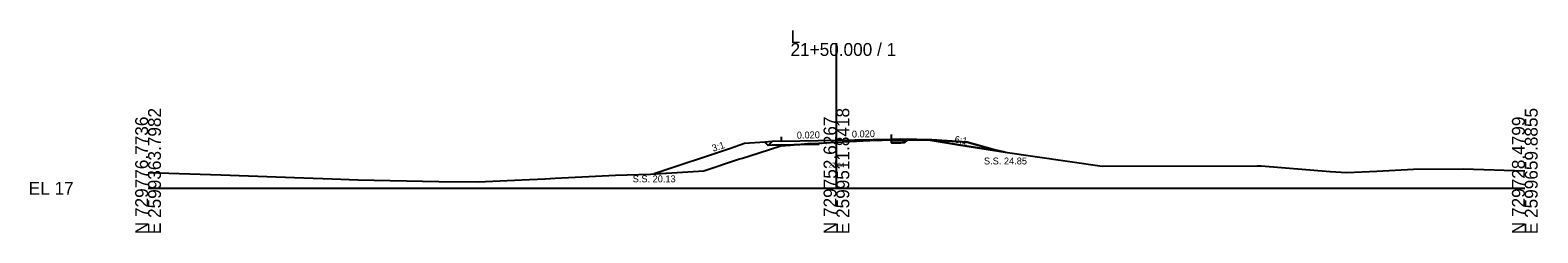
# Model space of a CAD drawing. Extents: x -26 to 3303, y -10 to 9555.
# Drawn here: x 1974.3 to 2302.8, y 2990.3 to 3034.4 of the extents above; entities that cross this region are included whole.
import ezdxf

# ---------------------------------------------------------------- set-up
doc = ezdxf.new("R2010")
doc.units = 0
for name, color, linetype in [('Exist Cross Section Cell', 7, 'Continuous'), ('Exist XS Center Line Elevation Label', 7, 'Continuous'), ('Exist XS Ground Line', 7, 'Continuous'), ('Prop XS Ditch Slope Text', 7, 'Continuous'), ('Prop XS Dump Level', 7, 'Continuous'), ('Prop XS Earthwork Shape', 7, 'Continuous'), ('Prop XS EOT Tick Mark', 7, 'Continuous'), ('Prop XS Finish Grade', 7, 'Continuous'), ('Prop XS Finish Grade Earthwork', 7, 'Continuous'), ('Prop XS Finish Grade Paved Shoulder', 7, 'Continuous'), ('Prop XS Finish Grade Pavement', 7, 'Continuous'), ('Prop XS Pvmt Edge Slope', 7, 'Continuous'), ('Prop XS SE Text', 7, 'Continuous'), ('Prop XS Side Slope Text', 7, 'Continuous'), ('Prop XS SS Elevation Text', 7, 'Continuous'), ('Prop XS Subgrade Earthwork', 7, 'Continuous')]:
    doc.layers.add(name, color=color, linetype=linetype)

msp = doc.modelspace()

# ---------------------------------------------------------------- linework, layer by layer
at = {"layer": 'Exist Cross Section Cell'}
for p, q in [((2150, 3000), (2150, 3031.61)), ((2000, 3000), (2150, 3000)), ((2150, 3000), (2300, 3000))]:
    msp.add_line(p, q, dxfattribs=at)
at = {"layer": 'Exist XS Ground Line'}
msp.add_lwpolyline([(2000, 3003.47), (2015.86, 3002.95), (2033.96, 3002.26), (2040.14, 3002.02), (2045.7, 3001.81), (2063.36, 3001.5), (2071.92, 3001.37), (2081.47, 3001.81), (2086.53, 3002.03), (2088.71, 3002.18), (2101.87, 3002.84), (2109.5, 3003.07), (2114.12, 3003.39), (2121.1, 3003.77), (2128.68, 3006.34), (2129.5, 3006.57), (2130.89, 3007.02), (2137.91, 3009.24), (2140.02, 3009.39), (2143.79, 3009.71), (2146.11, 3009.85), (2150, 3010.04), (2155.82, 3010.31), (2158.73, 3010.46), (2159.99, 3010.47), (2170.81, 3010.54), (2176.31, 3010.15), (2178.47, 3010.05), (2184.43, 3008.38), (2186.78, 3007.85), (2193.3, 3006.9), (2207.89, 3004.82), (2241.68, 3004.88), (2242.58, 3004.86), (2257.58, 3003.62), (2261.24, 3003.41), (2267.72, 3003.69), (2275.74, 3004.16), (2286.57, 3004.22), (2300, 3003.78)], dxfattribs=at)
at = {"layer": 'Prop XS Dump Level'}
for p, q in [((2138, 3010.23), (2150, 3010.47)), ((2150, 3010.47), (2162, 3010.71))]:
    msp.add_line(p, q, dxfattribs=at)
at = {"layer": 'Prop XS Earthwork Shape'}
for points in [[(2137.91, 3009.24), (2140.02, 3009.39), (2140.74, 3009.45), (2138, 3009.39), (2136, 3009.35), (2135.15, 3009.34), (2134.43, 3010.06), (2130, 3009.71), (2126.91, 3008.68), (2110.25, 3003.13), (2114.12, 3003.39), (2121.1, 3003.77), (2128.68, 3006.34), (2129.5, 3006.57), (2130.89, 3007.02)], [(2110.25, 3003.13), (2114.12, 3003.39), (2121.1, 3003.77), (2128.68, 3006.34), (2129.5, 3006.57), (2130.89, 3007.02), (2137.91, 3009.24), (2140.02, 3009.39), (2140.74, 3009.45), (2138, 3009.39), (2136, 3009.35), (2135.15, 3009.34), (2134.43, 3010.06), (2130, 3009.71), (2126.91, 3008.68)], [(2143.79, 3009.71), (2146.11, 3009.85), (2146.11, 3009.56), (2140.74, 3009.45)], [(2143.79, 3009.71), (2146.11, 3009.85), (2146.11, 3009.56), (2140.74, 3009.45)], [(2162, 3009.87), (2162, 3010.48), (2165.39, 3010.5), (2164.82, 3009.93), (2164, 3009.91)], [(2162, 3010.48), (2165.39, 3010.5), (2164.82, 3009.93), (2164, 3009.91), (2162, 3009.87)], [(2165.39, 3010.5), (2169.51, 3010.53), (2165.57, 3010.69)], [(2165.39, 3010.5), (2165.57, 3010.69), (2169.51, 3010.53)], [(2170, 3010.51), (2176.63, 3009.46), (2186.78, 3007.85), (2184.43, 3008.38), (2178.47, 3010.05), (2176.31, 3010.15), (2170.81, 3010.54), (2169.51, 3010.53)], [(2178.47, 3010.05), (2184.43, 3008.38), (2186.78, 3007.85), (2176.63, 3009.46), (2170, 3010.51), (2169.51, 3010.53), (2170.81, 3010.54), (2176.31, 3010.15)]]:
    msp.add_lwpolyline(points, close=True, dxfattribs=at)
at = {"layer": 'Prop XS EOT Tick Mark'}
for p, q in [((2138, 3010.23), (2138, 3011.23)), ((2162, 3010.71), (2162, 3011.71))]:
    msp.add_line(p, q, dxfattribs=at)
at = {"layer": 'Prop XS Finish Grade'}
for p, q in [((2136, 3010.19), (2134.43, 3010.06)), ((2164, 3010.75), (2165.57, 3010.69))]:
    msp.add_line(p, q, dxfattribs=at)
at = {"layer": 'Prop XS Finish Grade Earthwork'}
for p, q in [((2130, 3009.71), (2126.91, 3008.68)), ((2134.43, 3010.06), (2130, 3009.71)), ((2165.57, 3010.69), (2170, 3010.51)), ((2170, 3010.51), (2176.63, 3009.46)), ((2176.63, 3009.46), (2186.78, 3007.85)), ((2126.91, 3008.68), (2110.25, 3003.13))]:
    msp.add_line(p, q, dxfattribs=at)
at = {"layer": 'Prop XS Finish Grade Paved Shoulder'}
for p, q in [((2138, 3010.23), (2136, 3010.19)), ((2162, 3010.71), (2164, 3010.75))]:
    msp.add_line(p, q, dxfattribs=at)
at = {"layer": 'Prop XS Finish Grade Pavement'}
for p, q in [((2138, 3010.23), (2150, 3010.47)), ((2150, 3010.47), (2162, 3010.71))]:
    msp.add_line(p, q, dxfattribs=at)
at = {"layer": 'Prop XS Pvmt Edge Slope'}
for p, q in [((2135.15, 3009.34), (2134.43, 3010.06)), ((2136, 3010.19), (2135.15, 3009.34)), ((2164, 3010.75), (2164.82, 3009.93)), ((2164.82, 3009.93), (2165.57, 3010.69))]:
    msp.add_line(p, q, dxfattribs=at)
at = {"layer": 'Prop XS Subgrade Earthwork'}
for p, q in [((2135.15, 3009.34), (2134.43, 3010.06)), ((2138, 3009.39), (2136, 3009.35)), ((2146.11, 3009.56), (2138, 3009.39)), ((2146.11, 3009.56), (2146.11, 3009.85)), ((2162, 3009.87), (2162, 3010.48)), ((2162, 3009.87), (2164, 3009.91)), ((2164, 3009.91), (2164.82, 3009.93)), ((2164.82, 3009.93), (2165.57, 3010.69)), ((2136, 3009.35), (2135.15, 3009.34))]:
    msp.add_line(p, q, dxfattribs=at)

# ---------------------------------------------------------------- texts
at = {"layer": 'Exist Cross Section Cell'}
for s, p in [('L', (2140, 3031.61)), ('21+50.000 / 1', (2140, 3028.81)), ('EL 17', (1974, 2998.6))]:
    msp.add_text(s, height=2.8, dxfattribs=at).set_placement(p)
for s, p in [('E 2599363.7982', (2002.8, 2990)), ('E 2599511.8418', (2152.8, 2990)), ('E 2599659.8855', (2302.8, 2990)), ('N 729776.7736', (2000, 2990)), ('N 729752.6267', (2150, 2990)), ('N 729728.4799', (2300, 2990))]:
    msp.add_text(s, height=2.8, rotation=90, dxfattribs=at).set_placement(p)
at = {"layer": 'Exist XS Center Line Elevation Label'}
msp.add_text('27.04', height=1, dxfattribs=at).set_placement((2148.26, 3004.54))
at = {"layer": 'Prop XS Ditch Slope Text'}
msp.add_text('6:1', height=1.5, rotation=350.5377, dxfattribs=at).set_placement((2175.65, 3009.96))
at = {"layer": 'Prop XS Dump Level'}
for s, height, p in [('Case1', 0.04, (2130, 3009.67)), ('Eop', 0.3, (2146.11, 3009.55)), ('Case1', 0.04, (2170, 3010.47)), ('Eop', 0.3, (2170.81, 3010.24))]:
    msp.add_text(s, height=height, dxfattribs=at).set_placement(p)
at = {"layer": 'Prop XS SE Text'}
for p in [(2153.38, 3011.04), (2141.38, 3010.8)]:
    msp.add_text('0.020', height=1.5, rotation=1.1458, dxfattribs=at).set_placement(p)
at = {"layer": 'Prop XS Side Slope Text'}
msp.add_text('3:1', height=1.5, rotation=18.4349, dxfattribs=at).set_placement((2123.15, 3007.93))
at = {"layer": 'Prop XS SS Elevation Text'}
for s, p in [('S.S. 24.85', (2182.15, 3005.19)), ('S.S. 20.13', (2105.6, 3001.3))]:
    msp.add_text(s, height=1.5, dxfattribs=at).set_placement(p)

doc.saveas('drawing.dxf')
